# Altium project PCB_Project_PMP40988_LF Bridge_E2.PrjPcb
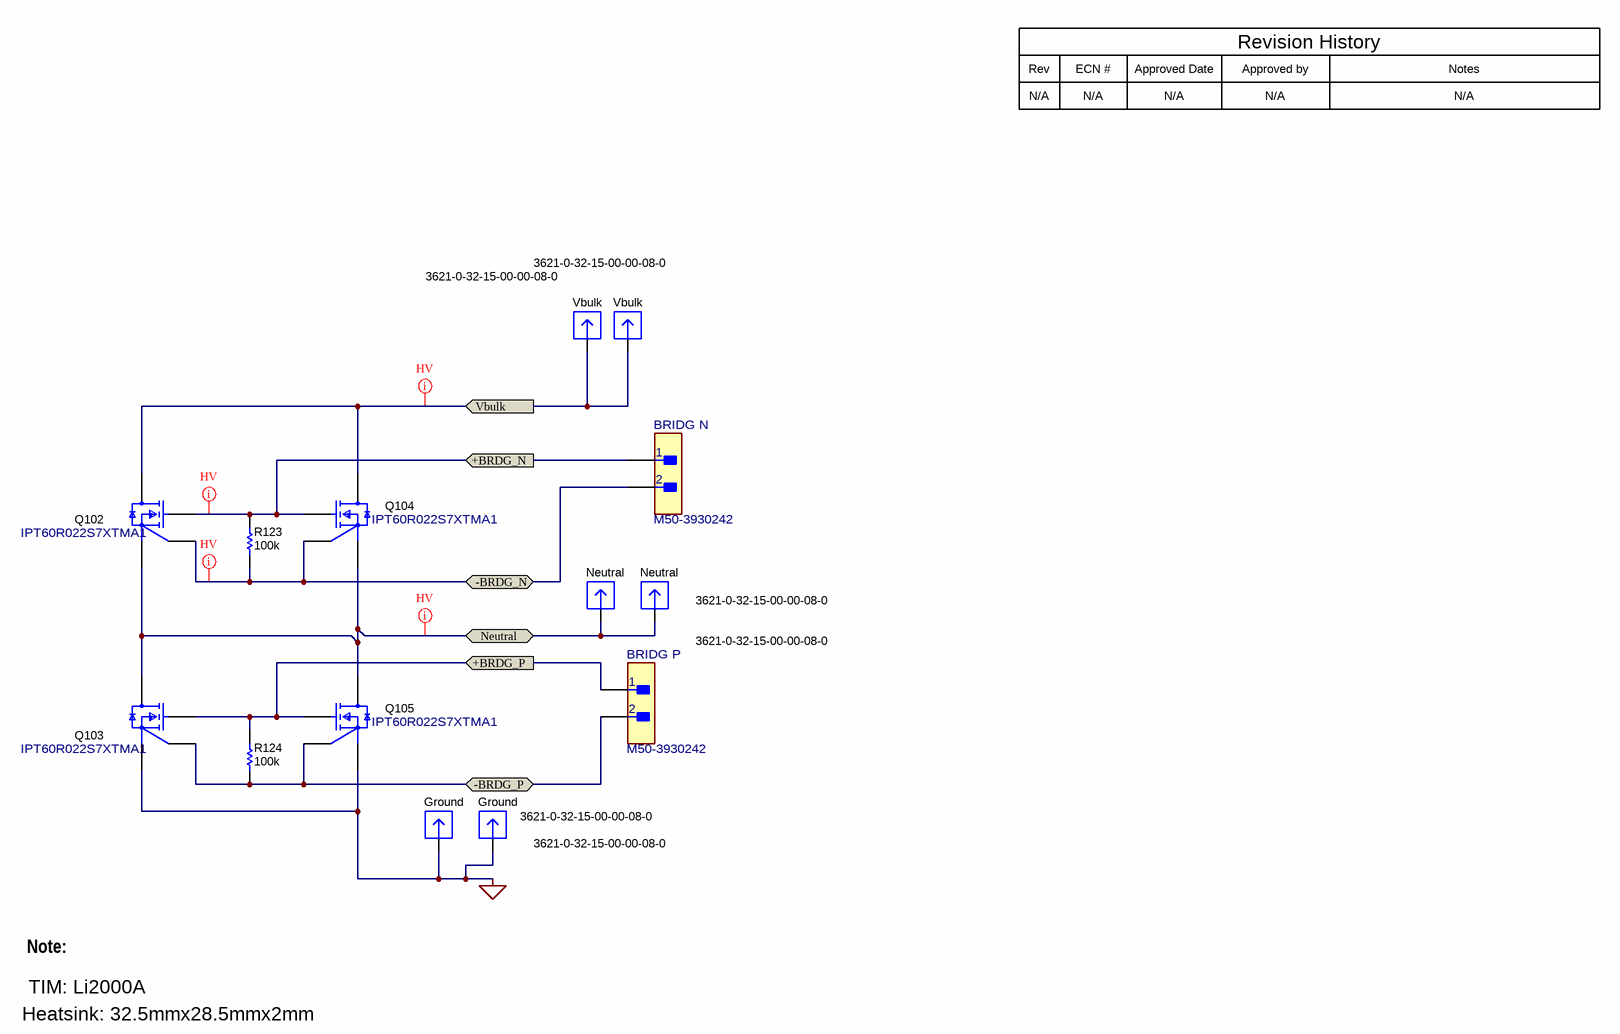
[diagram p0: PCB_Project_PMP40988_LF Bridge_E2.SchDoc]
CopyrightYear: 2022; PCB_Layout: Brent McDonald; PCB_Rev: E2; PRJ_Customer: Public Release; PRJ_Engineer: Brent McDonald; PRJ_Number: PMP40988_LF SR; PRJ_Title: PMP40988 LF SR Board; SCH_Rev: E2; TechSupport: http://www.ti.com/support; TID: N/A
1 sheet, 14 parts. Net scope: flat (ports and power ports of the same name join across sheets).
Board file: PCB_Project_PMP40988_LF Bridge_E2.PcbDoc

## Sheet PCB_Project_PMP40988_LF Bridge_E2.SchDoc
size 431 x 279 mm; Date: Not shown in title block; ApprovedBy: Not shown in title block; CheckedBy: Not shown in title block; Author: Not shown in title block; CompanyName: Not shown in title block; DrawnBy: San Chen; Engineer: Not shown in title block; Organization: Not shown in title block; Address1: Not shown in title block; Address2: Not shown in title block; Address3: Not shown in title block; Address4: Not shown in title block; DocumentNumber: 1; Revision: Use project parameter SCH_Rev; SheetNumber: 1; SheetTotal: 1; PageSetup: Record=PageOptions¦CenterHorizontal=True¦CenterVertical=True¦PrintScale=1.00¦XCorrection=1.00¦YCorrection=1.00¦PrintKind=0¦BorderSize=5000000¦LeftOffset=0¦BottomOffset=0¦Orientation=2¦PaperLength=1000¦PaperWidth=1000¦Scale=100¦PaperSource=15¦PrintQuality=600¦MediaType=1¦DitherType=10¦PaperKind=Letter¦PrintScaleMode=1

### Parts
(Parts that share a designator on the sheet are numbered #1, #2 ... from top to bottom, then left to right.)
BRIDG_N  M50-3930242  [FP-M50-3930242_HDR2-MFG]
BRIDG_P  M50-3930242  [FP-M50-3930242_HDR2-MFG]
Ground#1  3621-0-32-15-00-00-08-0  [Mill-Max_3621-0-32-xx-00-00-08-0]
Ground#2  3621-0-32-15-00-00-08-0  [Mill-Max_3621-0-32-xx-00-00-08-0]
Neutral#1  3621-0-32-15-00-00-08-0  [Mill-Max_3621-0-32-xx-00-00-08-0]
Neutral#2  3621-0-32-15-00-00-08-0  [Mill-Max_3621-0-32-xx-00-00-08-0]
Q102  IPT60R022S7XTMA1  [FP-IPT60R080G7XTMA1_HSOF-8-MFG]
Q103  IPT60R022S7XTMA1  [FP-IPT60R080G7XTMA1_HSOF-8-MFG]
Q104  IPT60R022S7XTMA1  [FP-IPT60R080G7XTMA1_HSOF-8-MFG]
Q105  IPT60R022S7XTMA1  [FP-IPT60R080G7XTMA1_HSOF-8-MFG]
R123  ValueDisplayed: 100k  [0603]  (hidden comment: RC0603FR-07100KL)
R124  ValueDisplayed: 100k  [0603]  (hidden comment: RC0603FR-07100KL)
Vbulk#1  3621-0-32-15-00-00-08-0  [Mill-Max_3621-0-32-xx-00-00-08-0]
Vbulk#2  3621-0-32-15-00-00-08-0  [Mill-Max_3621-0-32-xx-00-00-08-0]

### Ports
+BRDG_N (in), +BRDG_P (in), -BRDG_N (bidir), -BRDG_P (bidir), Neutral (bidir), Vbulk (in)

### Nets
PGND: Ground#1.1 Ground#2.1 Q103.3-4-5-6-7-8(Source) Q105.3-4-5-6-7-8(Source)
+BRDG_N: BRIDG_N.1 Q102.1(Gate) Q104.1(Gate) R123.2 ; port +BRDG_N
+BRDG_P: BRIDG_P.1 Q103.1(Gate) Q105.1(Gate) R124.2 ; port +BRDG_P
-BRDG_N: BRIDG_N.2 Q102.2(Driver_Source) Q104.2(Driver_Source) R123.1 ; port -BRDG_N
-BRDG_P: BRIDG_P.2 Q103.2(Driver_Source) Q105.2(Driver_Source) R124.1 ; port -BRDG_P
Neutral: Neutral#1.1 Neutral#2.1 Q102.3-4-5-6-7-8(Source) Q103.9(Drain) Q104.3-4-5-6-7-8(Source) Q105.9(Drain) ; port Neutral
Vbulk: Q102.9(Drain) Q104.9(Drain) Vbulk#1.1 Vbulk#2.1 ; port Vbulk

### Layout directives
net class HV: +BRDG_N, -BRDG_N, Neutral, Vbulk

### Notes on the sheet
- Rev
- N/A
- ECN #
- Approved Date
- Approved by
- Revision History
- Notes
- Note:
- TIM: Li2000A
- Heatsink: 32.5mmx28.5mmx2mm

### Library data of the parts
BRIDG_N BRIDG_P = CMP-0097272-1: Conn Unshrouded HDR 2 POS 1.27mm Solder RA Through Hole Box; Manufacturer: Harwin; AEC Qualified: No; Row_Count: 1; Conn Gender: Male; Conn Orientation: Right Angle; SizeZ_mm: 2.3mm; Current_A: 1A; ContactFinish: Gold,Nickel
Ground#1 Ground#2 Neutral#1 Neutral#2 Vbulk#1 Vbulk#2 = CMP-0082316-1: PCB Pin, 0.04" DIA, Edge-Mount; Manufacturer: Mill-Max; CompType: PCB Pin; ContactFinish: Gold; Gender: Male; Row_Count: 1
Q102-Q105 = CMP-0086487-1: MOSFET N-CH 650V 23A HSOF-8; Manufacturer: Infineon; QgTyp_nC: 150nC @ 10V; Rdson45_ohm: 0.022; Vgs_V: 20V; AEC Qualified: No; ChMode: False; SizeZ_mm: 2.4mm
R123 R124 = CMP-0022735-5: RES, 100 k, 1%, 0.1 W, 0603; Manufacturer: Yageo; Power_W: 100mW; TempCo: 100 ppm/C; Value: 100k; EIA_Code: E96; SizeX_mm: 1.6; SizeY_mm: 0.8; SizeZ_mm: 1; Value2: 0.1W; SizeArea_mm2: 1.28; AEC Qualified: N; VDC_V: 75V; AEC Category: Q200; SizeAreaWB_mm2: 4.68

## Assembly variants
001: not fitted FID1 FID2 FID3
